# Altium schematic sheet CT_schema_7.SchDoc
size 274 x 160 mm
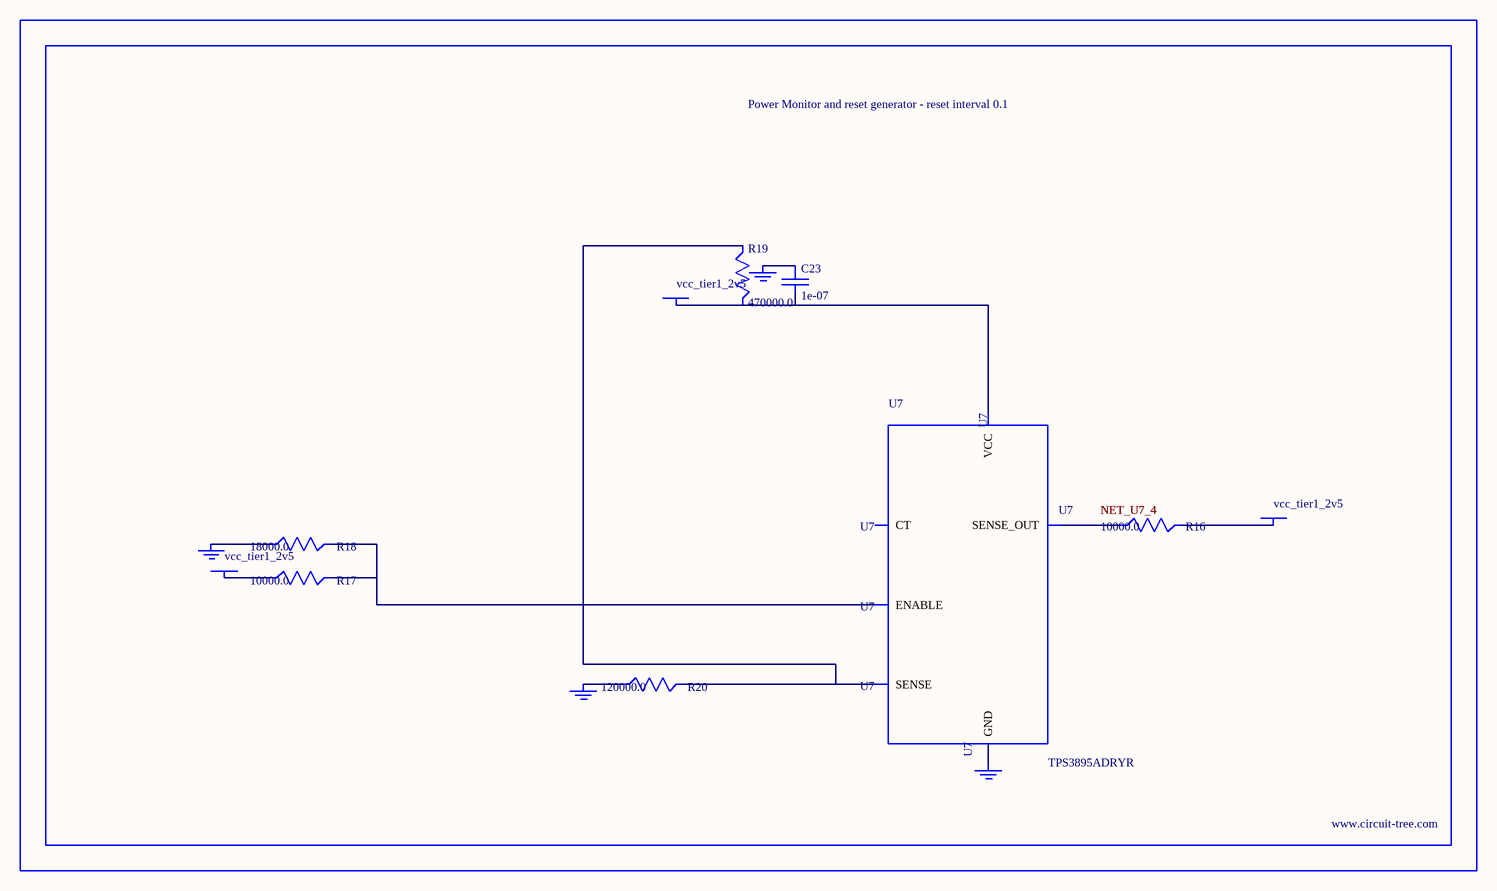
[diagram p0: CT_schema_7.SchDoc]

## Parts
BORDER6  (no value)
C23  1e-07  [C0402]
GND_INSTANCE_6_0  (no value)
GND_INSTANCE_6_1  (no value)
GND_INSTANCE_6_2  (no value)
GND_INSTANCE_6_3  (no value)
POWER_INSTANCE_6_0  vcc_tier1_2v5
POWER_INSTANCE_6_1  vcc_tier1_2v5
POWER_INSTANCE_6_2  vcc_tier1_2v5
R16  10000.0  [R0603]
R17  10000.0  [R0603]
R18  18000.0  [R0603]
R19  470000.0  [R0603]
R20  120000.0  [R0603]
U7  TPS3895ADRYR  [SON-6]

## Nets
NetC23_1: C23.1 GND_INSTANCE_6_2.0(GND)
NetC23_2: C23.2 POWER_INSTANCE_6_2.0(PWR) R19.2 U7.6(VCC)
NetGND_INSTANCE_6_0_0: GND_INSTANCE_6_0.0(GND) R18.1
NetGND_INSTANCE_6_1_0: GND_INSTANCE_6_1.0(GND) R20.1
NetGND_INSTANCE_6_3_0: GND_INSTANCE_6_3.0(GND) U7.2(GND)
NetPOWER_INSTANCE_6_0_0: POWER_INSTANCE_6_0.0(PWR) R17.1
NetPOWER_INSTANCE_6_1_0: POWER_INSTANCE_6_1.0(PWR) R16.2
NetR16_1: R16.1 U7.4(SENSE_OUT)
NetR17_2: R17.2 R18.2 U7.1(ENABLE)
NetR19_1: R19.1 R20.2 U7.3(SENSE)

Not connected (* = marked no-connect by the designer): U7 5(CT)

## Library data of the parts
BORDER6 = BORDER_PAGE6
C23 = C0402C104K3RACTU
GND_INSTANCE_6_0-GND_INSTANCE_6_3 = GND
POWER_INSTANCE_6_0-POWER_INSTANCE_6_2 = PWR
R16 R17 = RC0603JR-0710KL
R18 = RC0603JR-0718KL
R19 = RC0603JR-07470KL
R20 = RC0603JR-07120KL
